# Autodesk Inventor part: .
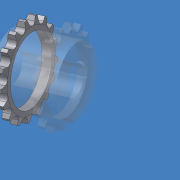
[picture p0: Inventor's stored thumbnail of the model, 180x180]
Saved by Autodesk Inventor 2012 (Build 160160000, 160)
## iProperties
Created: 2001-02
Part Number: .
Material: Steel, Mild
Document SubType Name: Modeling
Description: Kettentyp 12 B.
Density: 7.86 g/cm^3
+MSCProtocol1+ProtocolID: P00040914102026681
+MSCProtocol2+Protocol: P00040914102026681<@PID>[Version]<@EL>Version=2.2<@EL>[Files]<@EL>DataFile=SpiData|N023311<@EL>[CalcData]<@EL>IsMCW=0<@EL>[Synchronize]<@EL>ChangedVars=<@EL>[Ca
Company: CAD-Verlag
Control State: 0
Master: False
Checked Out: False
Shininess: 20.0
Length Units: 11269
Angle Units: 11279
Time Units: 11290
Mass Units: 11283
Length Display Precision: 3
Angle Display Precision: 2
TAB_typ: 12 B
TAB_d1: 12.07
TAB_t: 19.05
TAB_z0: 17
TAB_z1: 33
TAB_dd0: 103.674
TAB_dd1: 200.408
TAB_dd2: 0
TAB_dd3: 0
TAB_dfmin0: 91.604
TAB_dfmin1: 188.338
TAB_rimin: 6.095
TAB_remin0: 27.52
TAB_remin1: 50.694
TAB_alfamin0: 135
TAB_alfamin1: 137
Density: 7.860000000000001
Volumn: 4.275153872104327
Area: 21.350802561518744
PropertySet Name: Model Information
Author: Jürgen Kronas
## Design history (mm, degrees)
extrude "ExtrusionBlind1" new body distance "d3" = 19.46 (= msp_b); taper "d4" = 0 deg
  node "Sketch1" dims "d2" = 108.861 (= msp_d0)
sketch "Sketch4"
  geometry: A1 r 16.762 centre (0, 0) between (-16.62, -2.182) and (-15.921, -5.245) reference
hole "Hole1" sketch "Sketch4" diameter "d26" = 19.251 (= hole); stored, may be unused: countersink angle "d30" = 60 deg, drill point angle "d32" = 118 deg; dims "d27" = 6, "d28" = 4, "d29" = 2, "d31" = 8
sketch "Sketch5"
  geometry: L1 (0, -9.002)-(0, 20.171) reference; L2 (-54.431, 0)-(-54.431, 5.872); L3 (-54.431, 5.872)-(-45.802, 4.182); L4 (-45.802, 4.182)-(-38.502, 4.182); L5 (-38.502, 4.182)-(-38.502, 0); L6 (-38.502, 0)-(-38.502, -4.182); L7 (-38.502, -4.182)-(-45.802, -4.182); L8 (-45.802, -4.182)-(-54.431, -5.872); L9 (-54.431, -5.872)-(-54.431, 0); L10 (-54.431, 0)-(54.431, 0) reference; L11 (-54.431, 0)-(-54.431, 19.46) reference; A1 r 9.471 centre (-47, 0) between (-54.431, 5.872) and (-38.502, 4.182)
  constraints: 16 end point, 4 equal length, 4 parallel, 3 point on circle, 2 collinear, 1 centre point, 1 perpendicular, 1 point on line
  dimensions: "d33" = 8.364 distance between parallel lines of L7 L4 (= prf_e - prf_bf1); "d35" = 1.6898 vertical distance of L2.end L3.end (= msp_ba); "d36" = 91.604 diameter of L7.end L1 (= msp_df); "d37" = 77.004 diameter of L6 L1 (= msp_dg)
revolve "Revolution2" sketch "Sketch5" stored, may be unused: angle "d38" = 90 deg
pattern_linear "Rectangular Pattern2" dims "d41" = 19.46 (= prf_e)
sketch "Sketch6"
  geometry: L1 (0, 26.82)-(0, -20.115) reference; L2 (-20.115, 0)-(26.82, 0) reference; L3 (-7.961, 53.845)-(-5.302, 48.955); L4 (5.302, 48.955)-(7.961, 53.845); A1 r 6.035 centre (0, 51.837) between (-5.302, 48.955) and (5.302, 48.955); A2 r 54.431 centre (0, 0) between (7.961, 53.845) and (-7.961, 53.845); A3 r 54.431 centre (0, 0) between (-7.961, 53.845) and (7.961, 53.845) reference
  constraints: 6 point on circle, 4 end point, 2 centre point, 2 point on line, 2 tangent, 1 concentric, 1 equal length
  dimensions: "d42" = 103.674 diameter of A1.centre L2 (= msp_d); "d43" = 12.07 diameter of A1 (= prf_d1); "d44" = 57.0588 deg angle of L4 L3 (= msp_alfa)
extrude "Extrusion3" cut sketch "Sketch6" stored distance "d45" = 10; taper "d46" = 0 deg
pattern_circular "Circular Pattern2" dims angle "d49" = 360 deg
sketch "Skizze7"
  geometry: C1 r 38.502 at (0, 0) reference; C2 r 40 at (0, 0)
  constraints: 1 centre point, 1 coincident
  dimensions: "d53" = 80 diameter of C2
extrude "Extrusion4" cut sketch "Skizze7" stored distance "d54" = 10; taper "d55" = 0 deg
node "Volumenkörper1"
node "Volumenkörpern"
node "Oberflächenkörpern"
other parameters: "prf_bf1" = 11.096 [user parameter; used in 1 equation term], "prf_d1" = 12.07 [user parameter; used in 2 equation terms], "prf_e" = 19.46 [user parameter; used in 2 equation terms], "prf_dd0" = 103.674 [user parameter; used in 1 equation term], "prf_damin0" = 108.861 [user parameter; used in 1 equation term], "prf_dgmax0" = 77.004 [user parameter; used in 1 equation term], "prf_bk" = 19.46 [user parameter; used in 1 equation term], "msp_ba" = 1.6898 (= 0.14 x prf_d1) [user parameter; used in 1 equation term], "msp_d" = 103.674 (= prf_dd0) [user parameter; used in 1 equation term], "prf_dfmin0" = 91.604 [user parameter; used in 1 equation term], "msp_da" = 108.861 (= prf_damin0) [user parameter; used in 1 equation term], "msp_dg" = 77.004 (= prf_dgmax0) [user parameter; used in 2 equation terms], "msp_b" = 19.46 (= prf_bk) [user parameter; used in 1 equation term], "msp_df" = 91.604 (= prf_dfmin0) [user parameter; used in 1 equation term], "msp_alfa" = 57.0588 deg (computed from msp_z) [user parameter; used in 1 equation term], "msp_d0" = 108.861 (= msp_da) [user parameter; used in 1 equation term], "hole" = 19.251 (= 0.25 x msp_dg) [user parameter; used in 1 equation term], "d1" = 33.525 (derived), "d5" = 0, "d6" = 1.1914 (derived), "d8" = 6.7125 (derived), "d17" = 11.71864 (derived), "d19" = 8.51 (derived), "d52" = 0
